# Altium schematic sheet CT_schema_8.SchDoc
size 391 x 238 mm
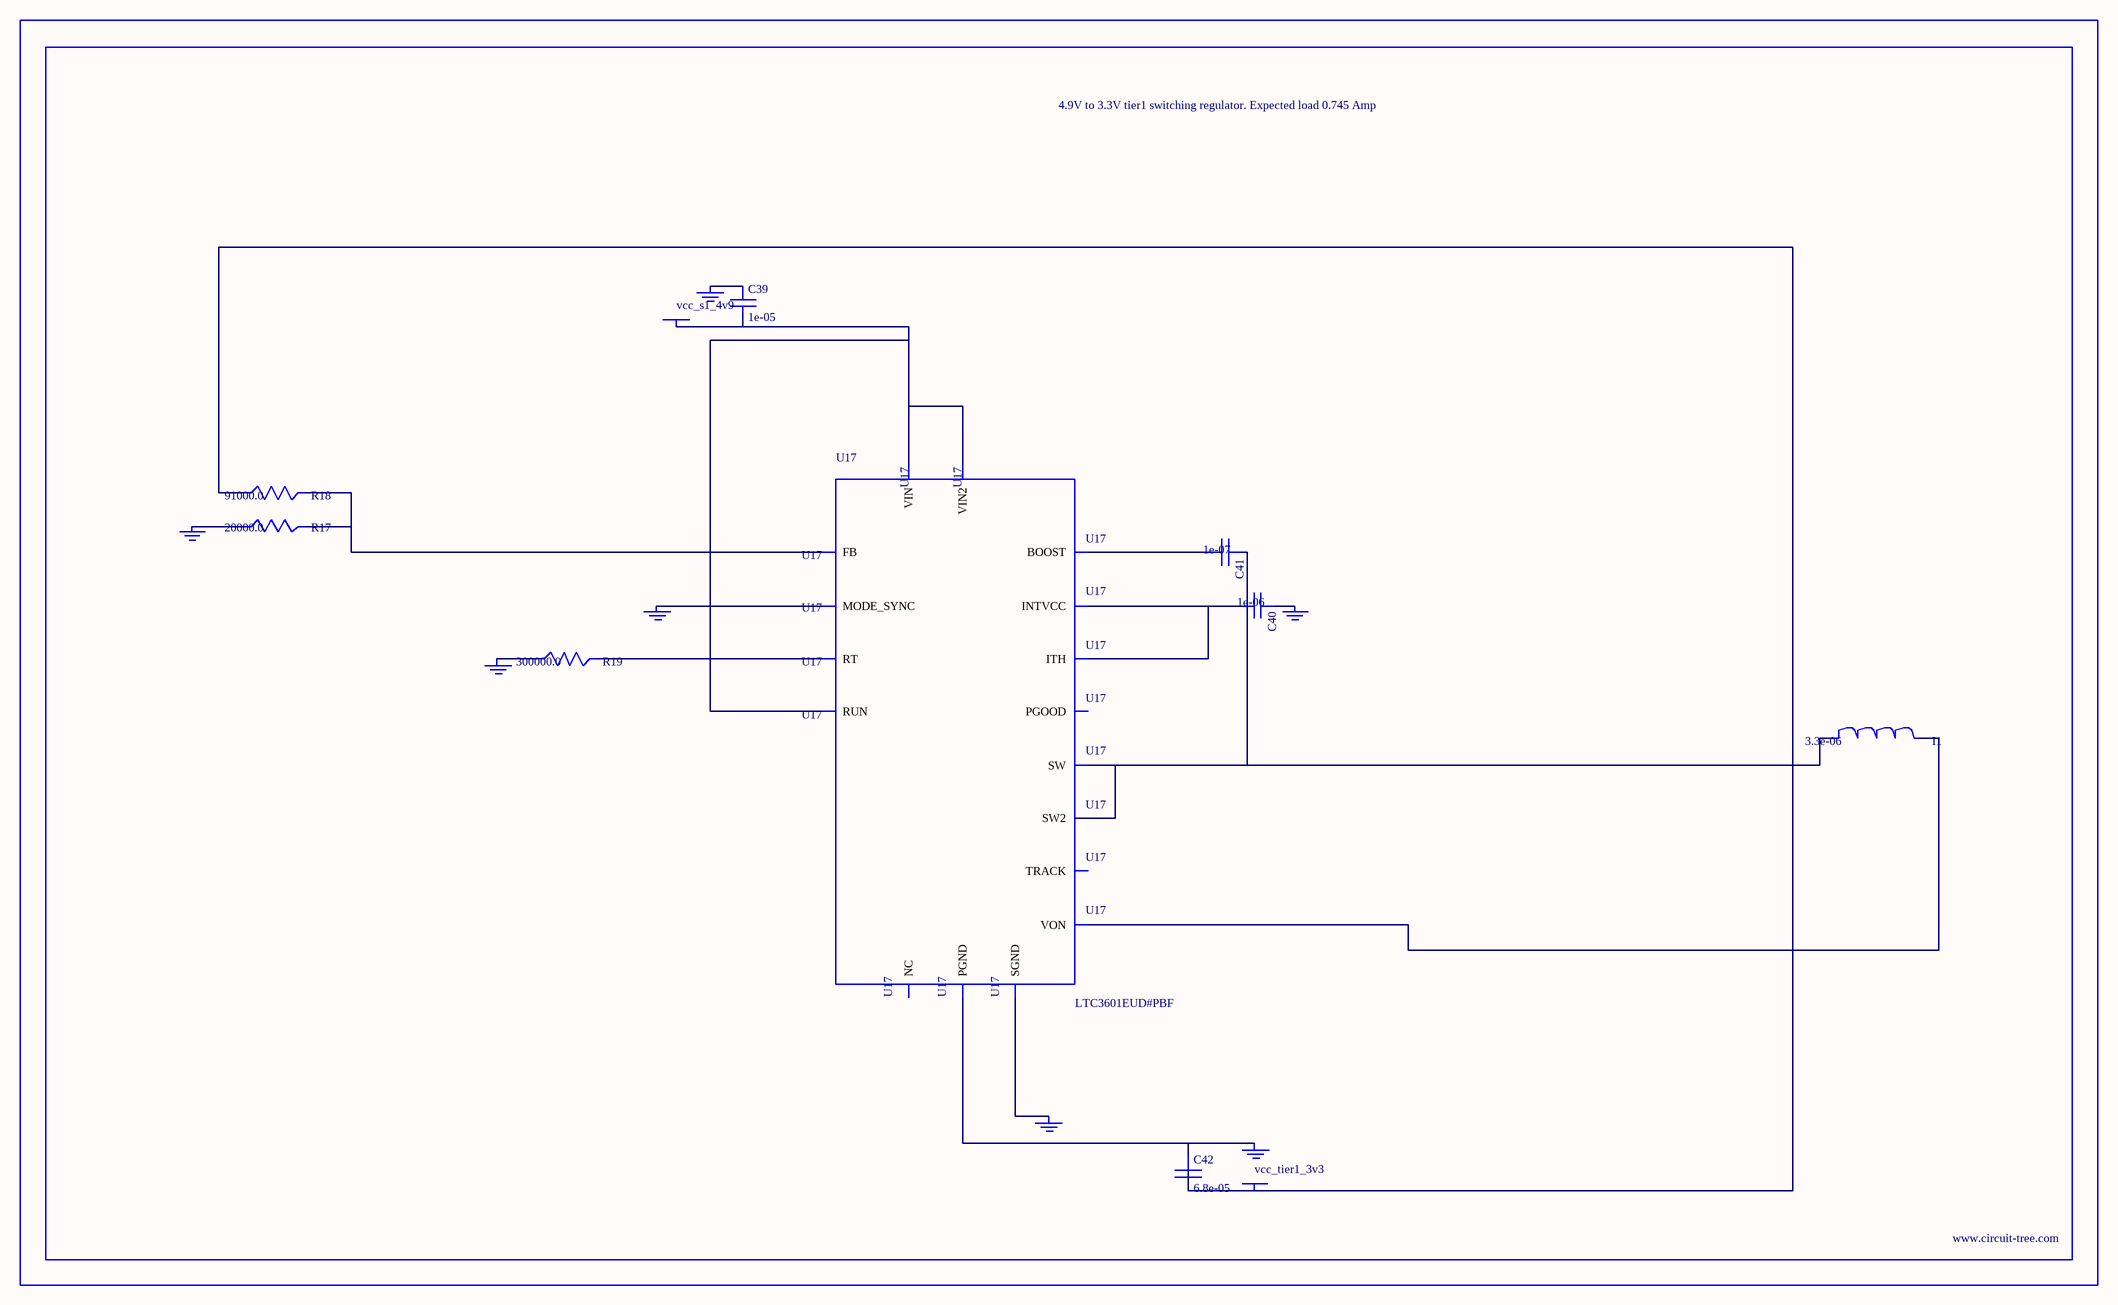
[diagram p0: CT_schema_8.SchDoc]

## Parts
BORDER7  (no value)
C39  1e-05  [C0805]
C40  1e-06  [C0603]
C41  1e-07  [C0402]
C42  6.8e-05  [2220]
GND_INSTANCE_7_0  (no value)
GND_INSTANCE_7_1  (no value)
GND_INSTANCE_7_2  (no value)
GND_INSTANCE_7_3  (no value)
GND_INSTANCE_7_4  (no value)
GND_INSTANCE_7_5  (no value)
GND_INSTANCE_7_6  (no value)
I1  3.3e-06  [WE-HCI_7030/7040/7050]
POWER_INSTANCE_7_0  vcc_s1_4v9
POWER_INSTANCE_7_1  vcc_tier1_3v3
R17  20000.0  [R0603]
R18  91000.0  [R0603]
R19  300000.0  [R0603]
U17  LTC3601EUD#PBF  [QFN-16_EP]

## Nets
NetC39_1: C39.1 GND_INSTANCE_7_5.0(GND)
NetC39_2: C39.2 POWER_INSTANCE_7_0.0(PWR) U17.14(RUN) U17.15(VIN) U17.16(VIN2)
NetC40_1: C40.1 GND_INSTANCE_7_1.0(GND)
NetC40_2: C40.2 U17.7(INTVCC) U17.12(ITH)
NetC41_1: C41.1 I1.1 U17.3(SW) U17.4(SW2)
NetC41_2: C41.2 U17.6(BOOST)
NetC42_1: C42.1 GND_INSTANCE_7_6.0(GND) U17.17(PGND)
NetC42_2: C42.2 I1.2 POWER_INSTANCE_7_1.0(PWR) R18.1 U17.8(VON)
NetGND_INSTANCE_7_0_0: GND_INSTANCE_7_0.0(GND) U17.1(MODE_SYNC)
NetGND_INSTANCE_7_2_0: GND_INSTANCE_7_2.0(GND) U17.9(SGND)
NetGND_INSTANCE_7_3_0: GND_INSTANCE_7_3.0(GND) R19.1
NetGND_INSTANCE_7_4_0: GND_INSTANCE_7_4.0(GND) R17.1
NetR17_2: R17.2 R18.2 U17.11(FB)
NetR19_2: R19.2 U17.10(RT)

Not connected (* = marked no-connect by the designer): U17 2(PGOOD) 5(NC) 13(TRACK)

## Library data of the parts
BORDER7 = BORDER_PAGE7
C39 = C0805C106K8RACTU
C40 = C0603C105K3RACTU
C41 = C0402C104K3RACTU
C42 = C5750X5R1A686M
GND_INSTANCE_7_0-GND_INSTANCE_7_6 = GND
I1 = 744314330
POWER_INSTANCE_7_0 POWER_INSTANCE_7_1 = PWR
R17 = RC0603JR-0720KL
R18 = RC0603JR-0791KL
R19 = RC0603JR-07300KL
